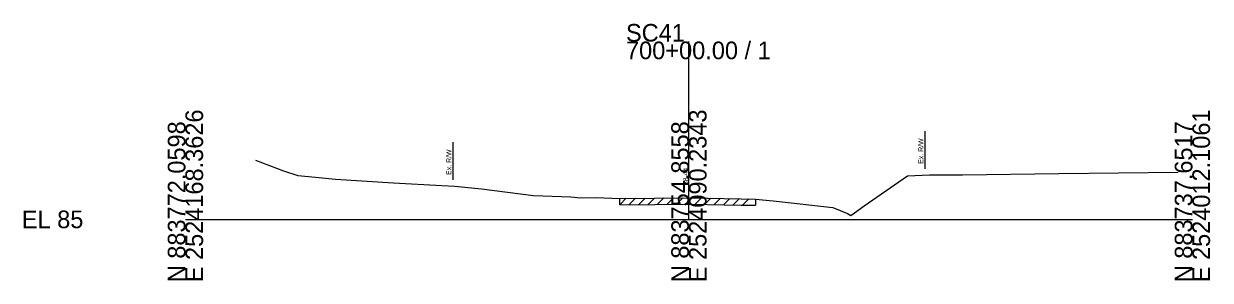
# Model space of a CAD drawing. Extents: x -26 to 183, y -10 to 24021.
# Drawn here: x -25.7 to 162.8, y 21990.3 to 22031.1 of the extents above; entities that cross this region are included whole.
import ezdxf

# ---------------------------------------------------------------- set-up
doc = ezdxf.new("R2010")
doc.units = 0
for name, color, linetype in [('RD_GPK_XS_Cell', 7, 'Continuous'), ('RD_XS_ExGround', 7, 'Continuous'), ('RD_XS_ExPaveRet', 7, 'Continuous'), ('RD_XS_ExRW', 7, 'Continuous'), ('RD_XS_TX_Elev_EX', 7, 'Continuous')]:
    doc.layers.add(name, color=color, linetype=linetype)

msp = doc.modelspace()

# ---------------------------------------------------------------- linework, layer by layer
at = {"layer": 'RD_GPK_XS_Cell'}
for p, q in [((80, 22000), (80, 22028.29)), ((0, 22000), (80, 22000)), ((80, 22000), (160, 22000))]:
    msp.add_line(p, q, dxfattribs=at)
at = {"layer": 'RD_XS_ExGround'}
for p, q in [((11.16, 22009.43), (15.58, 22007.72)), ((15.58, 22007.72), (17.84, 22006.97)), ((138.77, 22007.32), (157.74, 22007.5)), ((17.84, 22006.97), (20.68, 22006.7)), ((20.68, 22006.7), (23.83, 22006.42)), ((23.83, 22006.42), (33.08, 22005.84)), ((33.08, 22005.84), (40.72, 22005.41)), ((107.87, 22002.18), (114.75, 22006.93)), ((114.75, 22006.93), (118.22, 22007.08)), ((118.22, 22007.08), (123.49, 22007.07)), ((123.49, 22007.07), (138.77, 22007.32)), ((40.72, 22005.41), (42.8, 22005.28)), ((42.8, 22005.28), (47.03, 22004.88)), ((47.03, 22004.88), (55.28, 22003.78)), ((55.28, 22003.78), (61.26, 22003.57)), ((61.26, 22003.57), (62.78, 22003.45)), ((62.78, 22003.45), (65.22, 22003.49)), ((65.22, 22003.49), (69.02, 22003.34)), ((69.02, 22003.34), (74.59, 22003.39)), ((74.59, 22003.39), (80.26, 22003.44)), ((80.26, 22003.44), (88.29, 22003.28)), ((88.29, 22003.28), (90.56, 22003.24)), ((90.56, 22003.24), (93.38, 22002.93)), ((93.38, 22002.93), (102.89, 22001.91)), ((102.89, 22001.91), (105.22, 22000.91)), ((105.72, 22000.64), (107.87, 22002.18)), ((105.22, 22000.91), (105.72, 22000.64))]:
    msp.add_line(p, q, dxfattribs=at)
at = {"layer": 'RD_XS_ExPaveRet'}
for p, q in [((69.02, 22002.34), (70.03, 22003.35)), ((69.02, 22002.34), (69.02, 22003.34)), ((69.02, 22002.34), (74.59, 22002.39)), ((70.52, 22002.35), (71.53, 22003.36)), ((72.02, 22002.37), (73.03, 22003.38)), ((73.52, 22002.38), (74.53, 22003.39)), ((74.59, 22002.39), (80.26, 22002.44)), ((75.02, 22002.4), (76.03, 22003.41)), ((76.52, 22002.41), (77.53, 22003.42)), ((78.02, 22002.42), (79.03, 22003.43)), ((79.52, 22002.44), (80.52, 22003.44)), ((80.26, 22002.44), (88.29, 22002.28)), ((81.02, 22002.43), (82, 22003.41)), ((82.52, 22002.4), (83.5, 22003.38)), ((84.02, 22002.37), (85, 22003.35)), ((85.52, 22002.34), (86.5, 22003.32)), ((87.02, 22002.31), (88, 22003.29)), ((88.29, 22002.28), (90.56, 22002.24)), ((88.52, 22002.28), (89.5, 22003.26)), ((90.56, 22003.24), (90.56, 22002.24))]:
    msp.add_line(p, q, dxfattribs=at)
at = {"layer": 'RD_XS_ExRW'}
for p, q in [((117.5, 22014.05), (117.5, 22008.05)), ((42.5, 22012.3), (42.5, 22006.3))]:
    msp.add_line(p, q, dxfattribs=at)

# ---------------------------------------------------------------- texts
at = {"layer": 'RD_GPK_XS_Cell'}
for s, p in [('SC41', (70, 22028.29)), ('700+00.00 / 1', (70, 22025.49)), ('EL 85', (-26, 21998.6))]:
    msp.add_text(s, height=2.8, dxfattribs=at).set_placement(p)
for s, p in [('E 2524168.3626', (2.8, 21990)), ('E 2524090.2343', (82.8, 21990)), ('E 2524012.1061', (162.8, 21990)), ('N 883772.0598', (0, 21990)), ('N 883754.8558', (80, 21990)), ('N 883737.6517', (160, 21990))]:
    msp.add_text(s, height=2.8, rotation=90, dxfattribs=at).set_placement(p)
at = {"layer": 'RD_XS_ExRW'}
for p in [(117.25, 22008.84), (42.25, 22007.08)]:
    msp.add_text('Ex. R/W ', height=0.8, rotation=90, dxfattribs=at).set_placement(p)
at = {"layer": 'RD_XS_TX_Elev_EX'}
msp.add_text('88.44', height=0.8, rotation=90, dxfattribs=at).set_placement((79.9, 22005.44))

doc.saveas('drawing.dxf')
